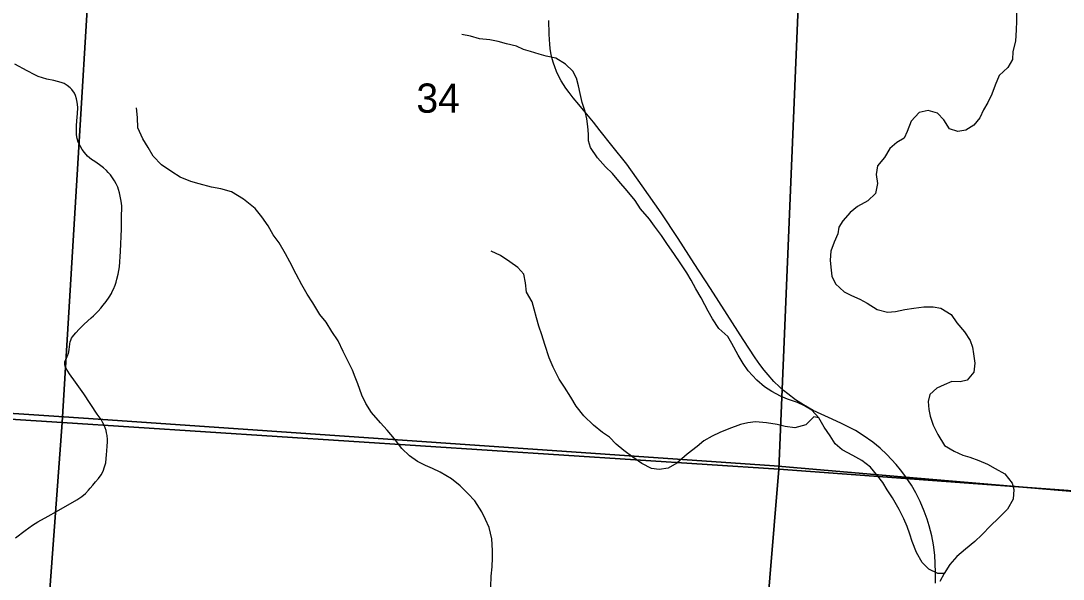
# Model space of a CAD drawing. Extents: x 0 to 34, y 0 to 22.
# Drawn here: x 3.758 to 5.252, y 19.293 to 20.093 of the extents above; entities that cross this region are included whole.
import ezdxf

# ---------------------------------------------------------------- set-up
doc = ezdxf.new("R2010")
doc.units = 0
for name, color, linetype in [('GM_X_Corporation', 7, 'Continuous'), ('GM_X_County_Road', 7, 'Continuous'), ('GM_X_Major_River', 7, 'Continuous'), ('GM_X_Minor_River', 7, 'Continuous'), ('GM_X_Section_Text', 7, 'Continuous'), ('GM_X_State_Route', 7, 'Continuous')]:
    doc.layers.add(name, color=color, linetype=linetype)

msp = doc.modelspace()

# ---------------------------------------------------------------- linework, layer by layer
at = {"layer": 'GM_X_Corporation'}
for points in [[(6.9348, 20.9), (2.1, 20.9), (2.1, 19.6396), (2.105, 19.6393), (2.5886, 19.6074), (3.0215, 19.5789), (3.8201, 19.5262), (3.8692, 19.5228), (4.8375, 19.4557), (5.0201, 19.4401), (5.6539, 19.3859), (5.9419, 19.3649), (6.5423, 19.3229), (6.824, 19.3005), (6.835, 19.4037), (6.8961, 20.3303), (6.9032, 20.4198)], [(3.8795, 20.5363), (3.8179, 19.5177), (2.8266, 19.5815), (2.8805, 20.5967)], [(4.8871, 20.4794), (4.8445, 19.4512), (3.8179, 19.5177), (3.8795, 20.5363)], [(4.8871, 20.4794), (5.901, 20.4176), (5.8355, 19.3781), (4.8445, 19.4512)], [(2.8266, 19.5815), (3.8179, 19.5177), (3.742, 18.4953), (2.7366, 18.558)], [(3.8179, 19.5177), (4.8445, 19.4512), (4.7598, 18.4308), (3.742, 18.4953)], [(4.8445, 19.4512), (5.8355, 19.3781), (5.775, 18.3681), (4.7598, 18.4308)]]:
    msp.add_lwpolyline(points, close=True, dxfattribs=at)
msp.add_lwpolyline([(6.7043, 17.4985), (6.7536, 18.2991), (6.7629, 18.3924), (6.7876, 18.7583), (6.824, 19.3005), (6.5423, 19.3229), (5.9419, 19.3649), (5.6539, 19.3859), (5.0201, 19.4401), (4.8375, 19.4557), (3.8692, 19.5228), (3.8201, 19.5262), (3.0215, 19.5789), (2.5886, 19.6074), (2.105, 19.6393), (2.1, 19.6396), (2.1, 16.1353)], dxfattribs=at)
at = {"layer": 'GM_X_County_Road'}
for points in [[(3.8738, 19.5212), (3.8733, 19.522), (3.8678, 19.5297), (3.8488, 19.5588), (3.837, 19.5758), (3.8281, 19.5874), (3.8232, 19.5951), (3.8218, 19.5985), (3.8216, 19.6006), (3.8215, 19.6029), (3.8217, 19.605), (3.8224, 19.6073), (3.8243, 19.611), (3.8259, 19.6148), (3.8266, 19.6166), (3.827, 19.6185), (3.8277, 19.6227), (3.828, 19.6257), (3.8286, 19.6303), (3.8292, 19.6335), (3.8302, 19.6359), (3.8312, 19.6385), (3.8325, 19.6405), (3.8343, 19.643), (3.8373, 19.6463), (3.8419, 19.6514), (3.8493, 19.6585), (3.8594, 19.6678), (3.8627, 19.6707), (3.8662, 19.6742), (3.8692, 19.6774), (3.8731, 19.6817), (3.8766, 19.686), (3.8807, 19.6911), (3.8851, 19.6974), (3.8881, 19.7026), (3.8892, 19.7057), (3.8911, 19.7087), (3.8936, 19.7147), (3.895, 19.7189), (3.8962, 19.7231), (3.898, 19.7301), (3.8998, 19.7408), (3.901, 19.7627), (3.9025, 19.795), (3.9026, 19.8108), (3.903, 19.8276), (3.9027, 19.832), (3.9018, 19.8373), (3.9009, 19.842), (3.8996, 19.8467), (3.8984, 19.8517), (3.8973, 19.8549), (3.8949, 19.8596), (3.8924, 19.8642), (3.8867, 19.8724), (3.8836, 19.8759), (3.8811, 19.8787), (3.877, 19.8826), (3.8713, 19.887), (3.8647, 19.8915), (3.8599, 19.8945), (3.854, 19.8995), (3.8495, 19.9044), (3.8462, 19.9089), (3.8433, 19.9139), (3.8408, 19.9195), (3.8392, 19.9247), (3.8381, 19.93), (3.838, 19.9346), (3.838, 19.9427), (3.8388, 19.9501), (3.8396, 19.9606), (3.8399, 19.9683), (3.8396, 19.9737), (3.8388, 19.9789), (3.838, 19.9815), (3.8368, 19.986), (3.8351, 19.9897), (3.8316, 19.9946), (3.8291, 19.9972), (3.8248, 20.0006), (3.8206, 20.0033), (3.8163, 20.0048), (3.8059, 20.0075), (3.7957, 20.0098), (3.7834, 20.0133), (3.7783, 20.0156), (3.7677, 20.0217), (3.7501, 20.0312)], [(3.7509, 19.3528), (3.7646, 19.3634), (3.775, 19.3707), (3.7827, 19.3756), (3.7977, 19.3837), (3.8094, 19.3903), (3.8385, 19.4071), (3.8458, 19.4121), (3.8509, 19.4163), (3.8555, 19.4209), (3.858, 19.4237), (3.8615, 19.4281), (3.8656, 19.4331), (3.8696, 19.4378), (3.8734, 19.4429), (3.8764, 19.4482), (3.8785, 19.4545), (3.88, 19.4602), (3.8814, 19.4719), (3.8818, 19.4767), (3.8823, 19.4845), (3.8825, 19.4895), (3.8824, 19.4933), (3.882, 19.4991), (3.8813, 19.5031), (3.8806, 19.5064), (3.8793, 19.5101), (3.8778, 19.5142), (3.8759, 19.5176), (3.8738, 19.5212)]]:
    msp.add_lwpolyline(points, dxfattribs=at)
at = {"layer": 'GM_X_Major_River'}
for points in [[(5.1846, 20.104), (5.1846, 20.0926), (5.1843, 20.0801), (5.1831, 20.0638), (5.1797, 20.049), (5.179, 20.0376), (5.1725, 20.0262), (5.1597, 20.0148), (5.1544, 20.0012), (5.1495, 19.9883), (5.1438, 19.9762), (5.1377, 19.9655), (5.1321, 19.9542), (5.1234, 19.9439), (5.112, 19.9363), (5.1007, 19.9348), (5.0886, 19.9386), (5.0807, 19.9511), (5.0716, 19.961), (5.058, 19.9647), (5.0455, 19.9617), (5.0338, 19.9496), (5.0281, 19.9348), (5.0239, 19.9249), (5.0134, 19.9188), (5.0035, 19.9105), (4.9956, 19.8976), (4.9858, 19.8854), (4.9835, 19.8729), (4.9858, 19.86), (4.9827, 19.8456), (4.9718, 19.8354), (4.957, 19.8274), (4.9464, 19.8187), (4.9362, 19.8069), (4.9302, 19.7974), (4.929, 19.7879), (4.9234, 19.7762), (4.9188, 19.7633), (4.9177, 19.7504), (4.9188, 19.7402), (4.9203, 19.7276), (4.9256, 19.7166), (4.9381, 19.7049), (4.9483, 19.6996), (4.9604, 19.6943), (4.9706, 19.6886), (4.9853, 19.6795), (5.0001, 19.6761), (5.0114, 19.6769), (5.0246, 19.6799), (5.0379, 19.6818), (5.0522, 19.6833), (5.0655, 19.6837)], [(5.0655, 19.6837), (5.0764, 19.6818), (5.0912, 19.6724), (5.0995, 19.6606), (5.1101, 19.6477), (5.1184, 19.6352), (5.1218, 19.6257), (5.1233, 19.6162), (5.1252, 19.603), (5.1237, 19.5897), (5.1142, 19.5787), (5.104, 19.576), (5.0919, 19.5764), (5.0813, 19.5718), (5.0707, 19.5669), (5.0605, 19.5578), (5.0583, 19.5479), (5.059, 19.5366), (5.0609, 19.5267), (5.0654, 19.5138), (5.0719, 19.5005), (5.0817, 19.485), (5.0953, 19.477), (5.1081, 19.4713), (5.118, 19.4683), (5.1308, 19.4634), (5.1433, 19.4581), (5.1543, 19.452), (5.1682, 19.4441), (5.1784, 19.4312), (5.1811, 19.4217), (5.1799, 19.408), (5.172, 19.3936), (5.1584, 19.3803), (5.1478, 19.3701), (5.1353, 19.3568), (5.1251, 19.3473), (5.1119, 19.3363), (5.0994, 19.3261), (5.0892, 19.3143), (5.0809, 19.3018), (5.0748, 19.29)]]:
    msp.add_lwpolyline(points, dxfattribs=at)
at = {"layer": 'GM_X_Minor_River'}
for points in [[(5.0809, 19.3018), (5.0722, 19.3018), (5.0593, 19.3078), (5.0495, 19.3173), (5.0416, 19.3317), (5.0355, 19.3473), (5.0321, 19.3579), (5.028, 19.3689), (5.0235, 19.3799), (5.0166, 19.3932), (5.0072, 19.4098), (4.9996, 19.4212), (4.9932, 19.4318), (4.9842, 19.4432), (4.9755, 19.4538), (4.963, 19.4633), (4.9505, 19.4705), (4.935, 19.4785), (4.9252, 19.4872), (4.9176, 19.4989), (4.9093, 19.5114), (4.9014, 19.5243), (4.8916, 19.5357), (4.881, 19.5418), (4.8708, 19.5463), (4.8568, 19.5512), (4.8466, 19.5558), (4.8345, 19.5622), (4.8239, 19.5687), (4.8129, 19.5785), (4.8005, 19.5918), (4.7933, 19.6024), (4.7861, 19.6142), (4.777, 19.6309), (4.7714, 19.6411), (4.7582, 19.6525), (4.7495, 19.6661), (4.743, 19.6771), (4.7381, 19.6866), (4.7328, 19.6964), (4.7253, 19.7093), (4.7189, 19.7215), (4.7124, 19.7321), (4.7037, 19.745), (4.6939, 19.7598), (4.6849, 19.7727), (4.6762, 19.7855), (4.6663, 19.7988), (4.6588, 19.809), (4.6459, 19.8238), (4.6384, 19.836), (4.627, 19.8496), (4.6153, 19.8636), (4.6059, 19.8746), (4.596, 19.8841), (4.5843, 19.897), (4.5745, 19.9118), (4.5715, 19.9213), (4.5715, 19.9307), (4.5707, 19.9417), (4.5692, 19.9527), (4.567, 19.9634), (4.5624, 19.9763), (4.5598, 19.9891), (4.5575, 20.0001), (4.5545, 20.0108), (4.5492, 20.021), (4.5386, 20.0312), (4.525, 20.0396), (4.511, 20.0426), (4.5012, 20.0452), (4.4884, 20.0494), (4.4785, 20.0521), (4.4683, 20.0566), (4.454, 20.0604), (4.4422, 20.0634), (4.4301, 20.0657), (4.4154, 20.0672), (4.4026, 20.071), (4.3901, 20.0736)], [(3.933, 19.9243), (3.9259, 19.9399), (3.9255, 19.9547), (3.924, 19.9683)], [(4.4319, 19.2825), (4.4322, 19.298), (4.4338, 19.3109), (4.4341, 19.3238), (4.4341, 19.3344), (4.4334, 19.3511), (4.4292, 19.3674), (4.4243, 19.3788), (4.4187, 19.3898), (4.4088, 19.4057), (4.3986, 19.4164), (4.388, 19.4273), (4.3752, 19.4372), (4.3593, 19.4467), (4.348, 19.452), (4.3382, 19.4561), (4.3268, 19.4618), (4.3151, 19.4702), (4.3041, 19.4808), (4.2936, 19.4944), (4.283, 19.5069), (4.2735, 19.5172), (4.2607, 19.532), (4.2528, 19.5452), (4.2467, 19.557), (4.241, 19.5733), (4.2373, 19.5828), (4.2335, 19.5926), (4.2255, 19.6089), (4.2203, 19.6196), (4.2131, 19.6347), (4.204, 19.6484), (4.1957, 19.6616), (4.1866, 19.6723), (4.1768, 19.6893), (4.1685, 19.7018), (4.1609, 19.7151), (4.153, 19.7303), (4.1436, 19.7481), (4.1375, 19.7595), (4.1284, 19.7754), (4.1201, 19.7868), (4.1126, 19.7997), (4.1039, 19.8122), (4.094, 19.8243), (4.0774, 19.8379), (4.06, 19.8482), (4.0449, 19.8523), (4.0317, 19.855), (4.0139, 19.8595), (4.0022, 19.8629), (3.9867, 19.869), (3.9746, 19.877), (3.9599, 19.8868), (3.9478, 19.8993), (3.941, 19.9118), (3.933, 19.9243)], [(4.9014, 19.5243), (4.8946, 19.5259), (4.8829, 19.5145), (4.8674, 19.5103), (4.8534, 19.5122), (4.8417, 19.5152), (4.8265, 19.5175), (4.811, 19.519), (4.7997, 19.5175), (4.7895, 19.5152), (4.7725, 19.5087), (4.7596, 19.5034), (4.7487, 19.4981), (4.737, 19.4916), (4.7271, 19.4837), (4.7131, 19.4723), (4.698, 19.4594), (4.6859, 19.4525), (4.6731, 19.4503), (4.6621, 19.4521), (4.6481, 19.4593), (4.6353, 19.4684), (4.6224, 19.4779), (4.6111, 19.487), (4.6016, 19.4969), (4.5918, 19.5037), (4.5786, 19.5139), (4.565, 19.5272), (4.554, 19.5412), (4.5461, 19.5541), (4.5374, 19.5685), (4.5295, 19.5799), (4.5208, 19.5973), (4.5151, 19.6106), (4.509, 19.6296), (4.5049, 19.6432), (4.5007, 19.6557), (4.497, 19.6679), (4.4939, 19.6804), (4.4909, 19.6906), (4.483, 19.7043), (4.4815, 19.7179), (4.4792, 19.7301), (4.4705, 19.7399), (4.4588, 19.7479), (4.4456, 19.757), (4.432, 19.7634)]]:
    msp.add_lwpolyline(points, dxfattribs=at)
at = {"layer": 'GM_X_State_Route'}
for points in [[(5.03, 19.4342), (5.0262, 19.4398), (5.0184, 19.4502), (5.0122, 19.4578), (4.999, 19.4721), (4.9894, 19.4809), (4.9788, 19.4895), (4.9651, 19.4992), (4.9539, 19.5063), (4.9427, 19.5123), (4.9342, 19.5164), (4.9208, 19.5226), (4.9048, 19.5296), (4.8935, 19.5352), (4.8797, 19.5431), (4.8683, 19.5505), (4.8571, 19.559), (4.8509, 19.5638), (4.8453, 19.569), (4.8373, 19.5767), (4.8288, 19.5859), (4.8231, 19.5929), (4.817, 19.6007), (4.8102, 19.6105), (4.7934, 19.6365), (4.7701, 19.6727), (4.7462, 19.7097), (4.723, 19.7458), (4.7001, 19.7814), (4.6758, 19.8179), (4.6487, 19.8567), (4.6265, 19.8876), (4.6053, 19.9147), (4.5884, 19.9355), (4.5787, 19.9478), (4.5694, 19.9593), (4.5644, 19.9654), (4.5577, 19.9733), (4.5499, 19.983), (4.5439, 19.9903), (4.539, 19.9967), (4.5357, 20.0017), (4.5324, 20.0072), (4.5292, 20.0133), (4.5258, 20.0206), (4.5233, 20.0274), (4.5213, 20.0325), (4.5196, 20.0385), (4.5182, 20.0448), (4.5169, 20.0528), (4.5162, 20.0601), (4.5156, 20.0661), (4.5153, 20.0743), (4.5146, 20.0938)], [(5.0685, 19.2876), (5.0689, 19.303), (5.0684, 19.3159), (5.0677, 19.3278), (5.066, 19.3426), (5.0635, 19.3554), (5.0597, 19.3697), (5.057, 19.3793), (5.0527, 19.391), (5.0468, 19.4046), (5.0405, 19.4169), (5.0343, 19.4279), (5.03, 19.4342)]]:
    msp.add_lwpolyline(points, dxfattribs=at)

# ---------------------------------------------------------------- texts
at = {"layer": 'GM_X_Section_Text'}
msp.add_text('34', height=0.04186, rotation=0, dxfattribs=at).set_placement((4.3251, 19.9615))

doc.saveas('drawing.dxf')
